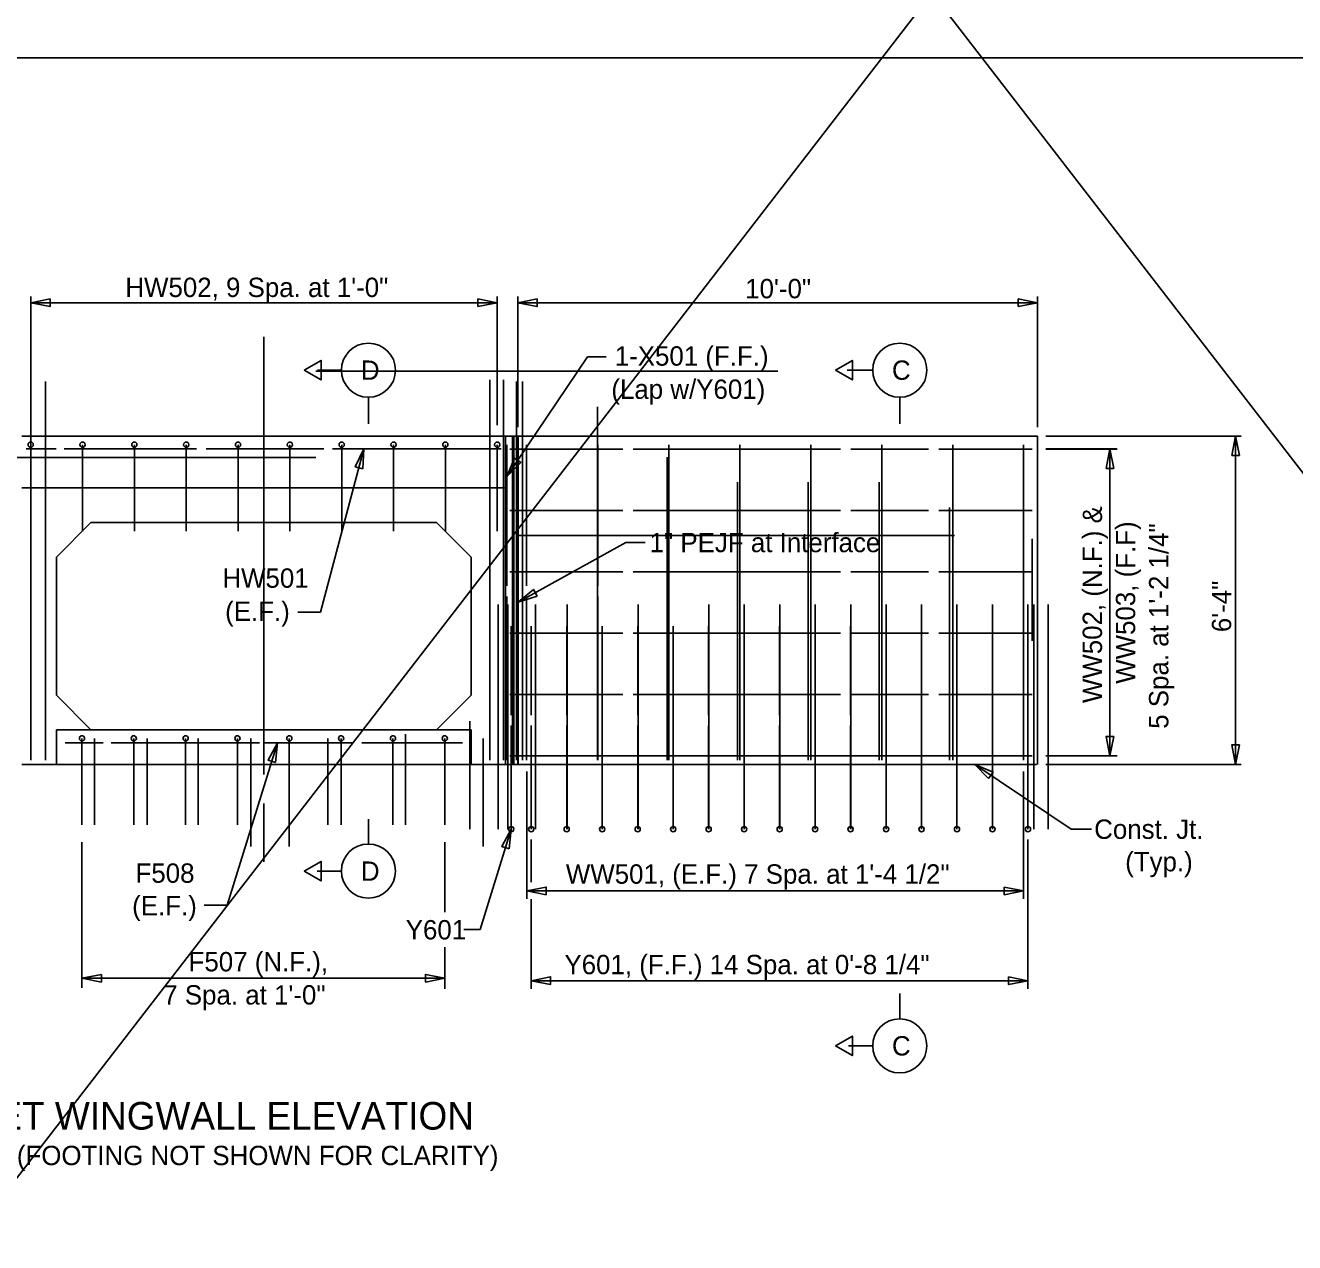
# Model space of a CAD drawing. Extents: x -1609 to 1184, y -412 to 394.
# Drawn here: x -1101.88 to -1077.4, y -122.95 to -99.47 of the extents above; entities that cross this region are included whole.
import ezdxf

# ---------------------------------------------------------------- set-up
doc = ezdxf.new("R2010")
doc.units = 0
for name, color, linetype in [('DR_P_Culvert', 7, 'Continuous'), ('SH_Border', 7, 'Continuous'), ('ST_Details', 7, 'Continuous'), ('ST_Text', 7, 'Continuous'), ('XS_P_Finished_Grade', 7, 'Continuous')]:
    doc.layers.add(name, color=color, linetype=linetype)

msp = doc.modelspace()

# ---------------------------------------------------------------- linework, layer by layer
at = {"layer": 'DR_P_Culvert'}
for p, q in [((-1096.279, -106.14), (-1087.363, -106.14)), ((-1092.457, -107.391), (-1092.457, -113.724)), ((-1092.383, -107.391), (-1092.383, -113.724)), ((-1092.373, -107.391), (-1092.373, -113.724)), ((-1101.868, -107.64), (-1101.285, -107.64)), ((-1101.779, -107.557), (-1101.779, -108.723)), ((-1100.779, -108.723), (-1100.779, -107.557)), ((-1099.779, -108.723), (-1099.779, -107.557)), ((-1098.779, -108.723), (-1098.779, -107.557)), ((-1097.779, -108.723), (-1097.779, -107.557)), ((-1096.779, -107.557), (-1096.779, -108.723)), ((-1095.956, -107.64), (-1092.7, -107.64)), ((-1095.779, -108.723), (-1095.779, -107.557)), ((-1094.779, -108.723), (-1094.779, -107.557)), ((-1093.779, -108.723), (-1093.779, -107.557)), ((-1092.779, -108.723), (-1092.779, -107.557)), ((-1096.279, -107.807), (-1105.214, -107.807)), ((-1101.779, -109.224), (-1101.779, -108.39)), ((-1100.779, -109.224), (-1100.779, -108.39)), ((-1099.779, -109.224), (-1099.779, -108.39)), ((-1098.779, -109.224), (-1098.779, -108.39)), ((-1097.779, -109.224), (-1097.779, -108.39)), ((-1096.779, -109.224), (-1096.779, -108.39)), ((-1095.779, -109.224), (-1095.779, -108.39)), ((-1094.779, -109.224), (-1094.779, -108.39)), ((-1093.779, -109.224), (-1093.779, -108.39)), ((-1092.779, -109.224), (-1092.779, -108.39)), ((-1093.307, -112.89), (-1093.307, -114.974)), ((-1101.117, -113.307), (-1100.379, -113.307)), ((-1100.79, -113.223), (-1100.79, -114.89)), ((-1100.79, -113.223), (-1100.79, -114.89)), ((-1100.548, -113.223), (-1100.548, -114.89)), ((-1099.79, -113.223), (-1099.79, -114.89)), ((-1099.79, -113.223), (-1099.79, -114.89)), ((-1099.534, -113.223), (-1099.534, -114.89)), ((-1098.79, -113.223), (-1098.79, -114.89)), ((-1098.79, -113.223), (-1098.79, -114.89)), ((-1098.548, -113.223), (-1098.548, -114.89)), ((-1097.79, -113.223), (-1097.79, -114.89)), ((-1097.79, -113.223), (-1097.79, -114.89)), ((-1097.534, -113.223), (-1097.534, -115.307)), ((-1096.79, -113.223), (-1096.79, -115.307)), ((-1096.79, -113.223), (-1096.79, -114.89)), ((-1096.048, -113.223), (-1096.048, -114.89)), ((-1095.79, -113.223), (-1095.79, -114.89)), ((-1095.79, -113.223), (-1095.79, -114.89)), ((-1095.388, -113.307), (-1093.45, -113.307)), ((-1094.79, -113.223), (-1094.79, -114.89)), ((-1094.79, -113.223), (-1094.79, -114.89)), ((-1094.548, -113.14), (-1094.548, -114.89)), ((-1093.79, -113.223), (-1093.79, -114.89)), ((-1093.79, -113.223), (-1093.79, -114.89)), ((-1093.048, -113.223), (-1093.048, -115.307))]:
    msp.add_line(p, q, dxfattribs=at)
msp.add_lwpolyline([(-1092.373, -107.391), (-1092.457, -107.391), (-1092.457, -113.724), (-1092.373, -113.724)], close=True, dxfattribs=at)
for points in [[(-1101.135, -107.64), (-1098.58, -107.64)], [(-1098.391, -107.64), (-1097.279, -107.64)], [(-1097.279, -107.64), (-1096.127, -107.64)], [(-1100.228, -113.307), (-1097.363, -113.307)], [(-1097.279, -113.307), (-1095.579, -113.307)]]:
    msp.add_lwpolyline(points, dxfattribs=at)
at = {"layer": 'SH_Border'}
msp.add_lwpolyline([(-1123.141, -100.094), (-1043.141, -100.094), (-1043.141, -152.594), (-1123.141, -152.594)], close=True, dxfattribs=at)
at = {"layer": 'ST_Details'}
for p, q in [((-1101.774, -106.341), (-1101.774, -113.64)), ((-1101.494, -106.341), (-1101.494, -113.64)), ((-1092.919, -106.307), (-1092.919, -113.64)), ((-1092.656, -106.307), (-1092.656, -113.64)), ((-1092.406, -106.341), (-1092.406, -113.64)), ((-1092.291, -106.341), (-1092.291, -113.64)), ((-1090.841, -106.827), (-1090.841, -113.64)), ((-1097.279, -107.391), (-1101.951, -107.391)), ((-1097.279, -107.391), (-1092.617, -107.391)), ((-1092.617, -107.391), (-1092.617, -113.724)), ((-1092.617, -107.391), (-1092.457, -107.391)), ((-1092.485, -107.391), (-1092.485, -113.724)), ((-1092.383, -107.391), (-1082.353, -107.391)), ((-1082.353, -107.391), (-1082.353, -113.724)), ((-1092.593, -107.557), (-1092.593, -110.283)), ((-1090.357, -107.641), (-1092.534, -107.641)), ((-1092.215, -107.557), (-1092.215, -110.283)), ((-1090.836, -107.558), (-1090.836, -110.283)), ((-1086.157, -107.641), (-1090.157, -107.641)), ((-1089.467, -107.558), (-1089.467, -110.283)), ((-1088.098, -107.558), (-1088.098, -110.283)), ((-1086.73, -107.558), (-1086.73, -110.283)), ((-1084.456, -107.641), (-1085.957, -107.641)), ((-1085.361, -107.558), (-1085.361, -110.283)), ((-1082.456, -107.641), (-1084.256, -107.641)), ((-1083.992, -107.558), (-1083.992, -110.283)), ((-1082.623, -107.557), (-1082.623, -111.254)), ((-1089.503, -107.797), (-1089.503, -113.64)), ((-1089.467, -107.797), (-1089.467, -113.64)), ((-1097.279, -108.39), (-1101.951, -108.39)), ((-1097.279, -108.39), (-1092.617, -108.39)), ((-1092.617, -113.724), (-1092.617, -108.39)), ((-1088.146, -108.283), (-1088.146, -113.64)), ((-1088.098, -108.283), (-1088.098, -113.64)), ((-1086.777, -108.283), (-1086.777, -113.64)), ((-1086.73, -108.283), (-1086.73, -113.64)), ((-1085.408, -108.283), (-1085.408, -113.64)), ((-1085.361, -108.283), (-1085.361, -113.64)), ((-1083.992, -108.283), (-1083.992, -113.64)), ((-1090.357, -108.824), (-1092.534, -108.824)), ((-1086.157, -108.824), (-1090.157, -108.824)), ((-1084.456, -108.824), (-1085.957, -108.824)), ((-1082.456, -108.824), (-1084.256, -108.824)), ((-1084.051, -108.768), (-1084.051, -113.64)), ((-1101.284, -109.724), (-1100.617, -109.057)), ((-1097.279, -109.057), (-1100.617, -109.057)), ((-1097.279, -109.057), (-1093.951, -109.057)), ((-1093.951, -109.057), (-1093.284, -109.724)), ((-1092.373, -109.307), (-1083.956, -109.307)), ((-1082.623, -109.253), (-1082.623, -113.64)), ((-1082.457, -109.371), (-1082.457, -111.342)), ((-1101.284, -112.39), (-1101.284, -109.724)), ((-1093.284, -112.39), (-1093.284, -109.724)), ((-1090.357, -110.007), (-1092.534, -110.007)), ((-1086.157, -110.007), (-1090.157, -110.007)), ((-1084.456, -110.007), (-1085.957, -110.007)), ((-1082.456, -110.007), (-1084.256, -110.007)), ((-1092.761, -110.64), (-1092.761, -114.974)), ((-1092.593, -110.483), (-1092.593, -113.64)), ((-1092.573, -110.64), (-1092.573, -114.974)), ((-1092.215, -110.483), (-1092.215, -113.64)), ((-1092.039, -110.64), (-1092.039, -114.974)), ((-1091.431, -110.641), (-1091.431, -114.974)), ((-1090.836, -110.483), (-1090.836, -113.64)), ((-1090.062, -110.64), (-1090.062, -114.974)), ((-1089.467, -113.64), (-1089.467, -110.483)), ((-1088.694, -110.64), (-1088.694, -114.974)), ((-1088.015, -110.641), (-1088.015, -114.974)), ((-1087.327, -110.64), (-1087.327, -114.974)), ((-1086.646, -110.641), (-1086.646, -114.974)), ((-1085.959, -110.64), (-1085.959, -114.974)), ((-1085.277, -110.641), (-1085.277, -114.974)), ((-1084.591, -110.64), (-1084.591, -114.974)), ((-1083.909, -110.641), (-1083.909, -114.974)), ((-1083.224, -110.64), (-1083.224, -114.974)), ((-1082.54, -110.64), (-1082.54, -114.974)), ((-1082.429, -110.64), (-1082.429, -114.974)), ((-1082.149, -110.64), (-1082.149, -114.974)), ((-1092.509, -111.057), (-1092.509, -112.774)), ((-1092.122, -111.057), (-1092.122, -112.774)), ((-1091.438, -112.774), (-1091.438, -111.057)), ((-1090.753, -111.057), (-1090.753, -114.974)), ((-1090.069, -112.774), (-1090.069, -111.057)), ((-1089.384, -111.057), (-1089.384, -114.974)), ((-1088.7, -112.774), (-1088.7, -111.057)), ((-1088.015, -112.774), (-1088.015, -111.057)), ((-1087.331, -112.774), (-1087.331, -111.057)), ((-1086.646, -112.774), (-1086.646, -111.057)), ((-1085.962, -112.774), (-1085.962, -111.057)), ((-1085.277, -112.774), (-1085.277, -111.057)), ((-1084.593, -112.774), (-1084.593, -111.057)), ((-1083.909, -112.774), (-1083.909, -111.057)), ((-1083.224, -112.774), (-1083.224, -111.057)), ((-1082.54, -112.774), (-1082.54, -111.057)), ((-1090.357, -111.19), (-1092.534, -111.19)), ((-1086.157, -111.19), (-1090.157, -111.19)), ((-1084.456, -111.19), (-1085.957, -111.19)), ((-1082.456, -111.19), (-1084.256, -111.19)), ((-1100.617, -113.057), (-1101.284, -112.39)), ((-1093.284, -112.39), (-1093.951, -113.057)), ((-1090.357, -112.374), (-1092.534, -112.374)), ((-1086.157, -112.374), (-1090.157, -112.374)), ((-1084.456, -112.374), (-1085.957, -112.374)), ((-1082.456, -112.374), (-1084.256, -112.374)), ((-1097.284, -113.057), (-1101.284, -113.057)), ((-1101.284, -113.724), (-1101.284, -113.057)), ((-1097.279, -113.057), (-1100.617, -113.057)), ((-1097.284, -113.057), (-1093.284, -113.057)), ((-1097.279, -113.057), (-1093.951, -113.057)), ((-1093.284, -113.724), (-1093.284, -113.057)), ((-1092.509, -112.974), (-1092.509, -114.974)), ((-1092.534, -113.557), (-1090.373, -113.557)), ((-1092.373, -113.557), (-1083.956, -113.557)), ((-1097.279, -113.724), (-1101.951, -113.724)), ((-1097.279, -113.724), (-1101.284, -113.724)), ((-1093.284, -113.724), (-1097.279, -113.724)), ((-1097.279, -113.724), (-1092.617, -113.724)), ((-1092.617, -113.724), (-1082.373, -113.724))]:
    msp.add_line(p, q, dxfattribs=at)
for points in [[(-1088.098, -110.483), (-1088.098, -113.64)], [(-1086.73, -110.483), (-1086.73, -113.64)], [(-1085.361, -110.483), (-1085.361, -113.64)], [(-1083.992, -110.483), (-1083.992, -113.64)], [(-1082.623, -111.454), (-1082.623, -113.64)], [(-1092.122, -112.974), (-1092.122, -114.974)], [(-1091.438, -114.974), (-1091.438, -112.974)], [(-1090.069, -114.974), (-1090.069, -112.974)], [(-1088.7, -114.974), (-1088.7, -112.974)], [(-1088.015, -114.974), (-1088.015, -112.974)], [(-1087.331, -114.974), (-1087.331, -112.974)], [(-1086.646, -114.974), (-1086.646, -112.974)], [(-1085.962, -114.974), (-1085.962, -112.974)], [(-1085.277, -114.974), (-1085.277, -112.974)], [(-1084.593, -114.974), (-1084.593, -112.974)], [(-1083.909, -114.974), (-1083.909, -112.974)], [(-1083.224, -114.974), (-1083.224, -112.974)], [(-1082.54, -114.974), (-1082.54, -112.974)], [(-1086.157, -113.557), (-1090.157, -113.557)], [(-1084.456, -113.557), (-1085.957, -113.557)], [(-1082.456, -113.557), (-1084.256, -113.557)]]:
    msp.add_lwpolyline(points, dxfattribs=at)
msp.add_lwpolyline([(-1086.251, -119.154), (-1085.927, -118.966), (-1085.927, -119.341)], close=True, dxfattribs=at)
for centre in [(-1101.779, -107.557), (-1100.779, -107.557), (-1099.779, -107.557), (-1098.779, -107.557), (-1097.779, -107.557), (-1096.779, -107.557), (-1095.779, -107.557), (-1094.779, -107.557), (-1093.779, -107.557), (-1092.779, -107.557), (-1100.79, -113.223), (-1099.79, -113.223), (-1098.79, -113.223), (-1097.79, -113.223), (-1096.79, -113.223), (-1095.79, -113.223), (-1094.79, -113.223), (-1093.79, -113.223), (-1092.509, -114.974), (-1092.122, -114.974), (-1091.438, -114.974), (-1090.753, -114.974), (-1090.069, -114.974), (-1089.384, -114.974), (-1088.7, -114.974), (-1088.015, -114.974), (-1087.331, -114.974), (-1086.646, -114.974), (-1085.962, -114.974), (-1085.277, -114.974), (-1084.593, -114.974), (-1083.909, -114.974), (-1083.224, -114.974), (-1082.54, -114.974)]:
    msp.add_circle(centre, 0.0502, dxfattribs=at)
at = {"layer": 'ST_Text'}
for p, q in [((-1101.779, -107.178), (-1101.779, -104.7)), ((-1092.779, -107.178), (-1092.779, -104.7)), ((-1092.383, -107.221), (-1092.383, -104.7)), ((-1082.353, -107.221), (-1082.353, -104.7)), ((-1101.779, -104.818), (-1092.779, -104.818)), ((-1082.353, -104.818), (-1092.383, -104.818)), ((-1097.284, -113.918), (-1097.284, -105.475)), ((-1092.593, -108.171), (-1091.035, -105.864)), ((-1091.035, -105.864), (-1090.677, -105.864)), ((-1095.785, -106.12), (-1096.248, -106.12)), ((-1085.535, -106.12), (-1086.03, -106.12)), ((-1095.263, -106.642), (-1095.263, -107.156)), ((-1085.013, -106.642), (-1085.013, -107.156)), ((-1078.427, -107.391), (-1082.194, -107.391)), ((-1078.534, -107.391), (-1078.534, -113.724)), ((-1095.352, -107.64), (-1096.19, -110.791)), ((-1082.194, -107.64), (-1080.832, -107.64)), ((-1082.194, -107.641), (-1080.822, -107.641)), ((-1080.96, -113.557), (-1080.96, -107.641)), ((-1092.373, -110.594), (-1090.296, -109.444)), ((-1089.922, -109.444), (-1090.296, -109.444)), ((-1096.626, -110.791), (-1096.19, -110.791)), ((-1097.018, -113.307), (-1097.99, -116.437)), ((-1082.194, -113.557), (-1080.822, -113.557)), ((-1083.564, -113.724), (-1081.706, -114.974)), ((-1082.623, -113.86), (-1082.623, -116.321)), ((-1082.194, -113.724), (-1078.427, -113.724)), ((-1092.205, -113.863), (-1092.205, -116.321)), ((-1097.284, -115.606), (-1097.284, -114.481)), ((-1095.263, -115.261), (-1095.263, -114.781)), ((-1092.509, -114.974), (-1093.11, -116.908)), ((-1081.317, -114.974), (-1081.706, -114.974)), ((-1100.79, -115.223), (-1100.79, -118.034)), ((-1093.79, -115.223), (-1093.79, -116.576)), ((-1092.122, -115.171), (-1092.122, -115.999)), ((-1082.54, -115.171), (-1082.54, -118.055)), ((-1095.785, -115.783), (-1096.253, -115.783)), ((-1092.205, -116.165), (-1082.623, -116.165)), ((-1098.43, -116.437), (-1097.99, -116.437)), ((-1092.122, -116.325), (-1092.122, -118.055)), ((-1093.423, -116.908), (-1093.11, -116.908)), ((-1093.79, -117.253), (-1093.79, -118.055)), ((-1093.79, -117.851), (-1100.79, -117.851)), ((-1092.122, -117.897), (-1082.54, -117.897)), ((-1085.013, -118.632), (-1085.013, -118.142)), ((-1085.535, -119.154), (-1086.001, -119.154))]:
    msp.add_line(p, q, dxfattribs=at)
for points in [[(-1101.406, -104.744), (-1101.779, -104.818), (-1101.406, -104.893)], [(-1093.152, -104.893), (-1092.779, -104.818), (-1093.152, -104.744)], [(-1092.009, -104.744), (-1092.383, -104.818), (-1092.009, -104.893)], [(-1082.727, -104.893), (-1082.353, -104.818), (-1082.727, -104.744)], [(-1096.501, -106.12), (-1096.177, -105.932), (-1096.177, -106.307)], [(-1086.251, -106.12), (-1085.927, -105.932), (-1085.927, -106.307)], [(-1078.609, -107.764), (-1078.534, -107.391), (-1078.459, -107.764)], [(-1095.372, -108.021), (-1095.352, -107.64), (-1095.517, -107.984)], [(-1081.034, -108.014), (-1080.96, -107.64), (-1080.885, -108.014)], [(-1092.445, -107.82), (-1092.593, -108.171), (-1092.321, -107.904)], [(-1092.01, -110.48), (-1092.373, -110.594), (-1092.082, -110.349)], [(-1097.058, -113.685), (-1097.018, -113.307), (-1097.2, -113.641)], [(-1080.885, -113.184), (-1080.96, -113.557), (-1081.034, -113.184)], [(-1078.459, -113.35), (-1078.534, -113.724), (-1078.609, -113.35)], [(-1083.298, -113.996), (-1083.564, -113.724), (-1083.214, -113.873)], [(-1092.549, -115.352), (-1092.509, -114.974), (-1092.691, -115.308)], [(-1096.501, -115.783), (-1096.177, -115.596), (-1096.177, -115.971)], [(-1091.832, -116.239), (-1092.205, -116.165), (-1091.832, -116.09)], [(-1082.996, -116.09), (-1082.623, -116.165), (-1082.996, -116.239)], [(-1100.416, -117.776), (-1100.79, -117.851), (-1100.416, -117.925)], [(-1094.163, -117.925), (-1093.79, -117.851), (-1094.163, -117.776)], [(-1091.749, -117.971), (-1092.122, -117.897), (-1091.749, -117.822)], [(-1082.913, -117.822), (-1082.54, -117.897), (-1082.913, -117.971)]]:
    msp.add_lwpolyline(points, close=True, dxfattribs=at)
for centre in [(-1095.263, -106.12), (-1085.013, -106.12), (-1095.263, -115.783), (-1085.013, -119.154)]:
    msp.add_circle(centre, 0.522, dxfattribs=at)
at = {"layer": 'XS_P_Finished_Grade'}
for p, q in [((-1126.891, -43.844), (-1041.891, -153.844)), ((-1126.891, -153.844), (-1041.891, -43.844))]:
    msp.add_line(p, q, dxfattribs=at)

# ---------------------------------------------------------------- texts
at = {"layer": 'ST_Text'}
for s, height, p in [('HW502, 9 Spa. at 1\'-0"', 0.37335, (-1099.953, -104.709)), ('10\'-0"', 0.3733, (-1087.995, -104.733)), ('1-X501 (F.F.)', 0.37335, (-1090.512, -106.033)), ('D', 0.373, (-1095.408, -106.306)), ('C', 0.373, (-1085.163, -106.306)), ('(Lap w/Y601)', 0.37335, (-1090.577, -106.673)), ('1" PEJF at Interface', 0.37335, (-1089.839, -109.631)), ('HW501', 0.3733, (-1098.081, -110.317)), ('(E.F.)', 0.3733, (-1098.028, -110.957)), ('Const. Jt.', 0.3733, (-1081.262, -115.161)), ('(Typ.)', 0.3733, (-1080.664, -115.788)), ('F508', 0.3733, (-1099.757, -116.008)), ('D', 0.373, (-1095.408, -115.97)), ('WW501, (E.F.) 7 Spa. at 1\'-4 1/2"', 0.37335, (-1091.455, -116.026)), ('(E.F.)', 0.3733, (-1099.822, -116.636)), ('Y601', 0.3733, (-1094.544, -117.101)), ('F507 (N.F.),', 0.37335, (-1098.733, -117.717)), ('Y601, (F.F.) 14 Spa. at 0\'-8 1/4"', 0.37335, (-1091.482, -117.772)), ('7 Spa. at 1\'-0"', 0.37335, (-1099.222, -118.357)), ('C', 0.373, (-1085.163, -119.34)), ('OUTLET WINGWALL ELEVATION', 0.53335, (-1104.324, -120.77)), ('(FOOTING NOT SHOWN FOR CLARITY)', 0.37335, (-1102.046, -121.455))]:
    msp.add_text(s, height=height, dxfattribs=at).set_placement(p)
for s, height, p in [('WW502, (N.F.) &', 0.37335, (-1081.111, -112.542)), ('WW503, (F.F)', 0.37335, (-1080.471, -112.17)), ('5 Spa. at 1\'-2 1/4"', 0.37335, (-1079.831, -113.038)), ('6\'-4"', 0.3733, (-1078.619, -111.174))]:
    msp.add_text(s, height=height, rotation=90, dxfattribs=at).set_placement(p)

doc.saveas('drawing.dxf')
